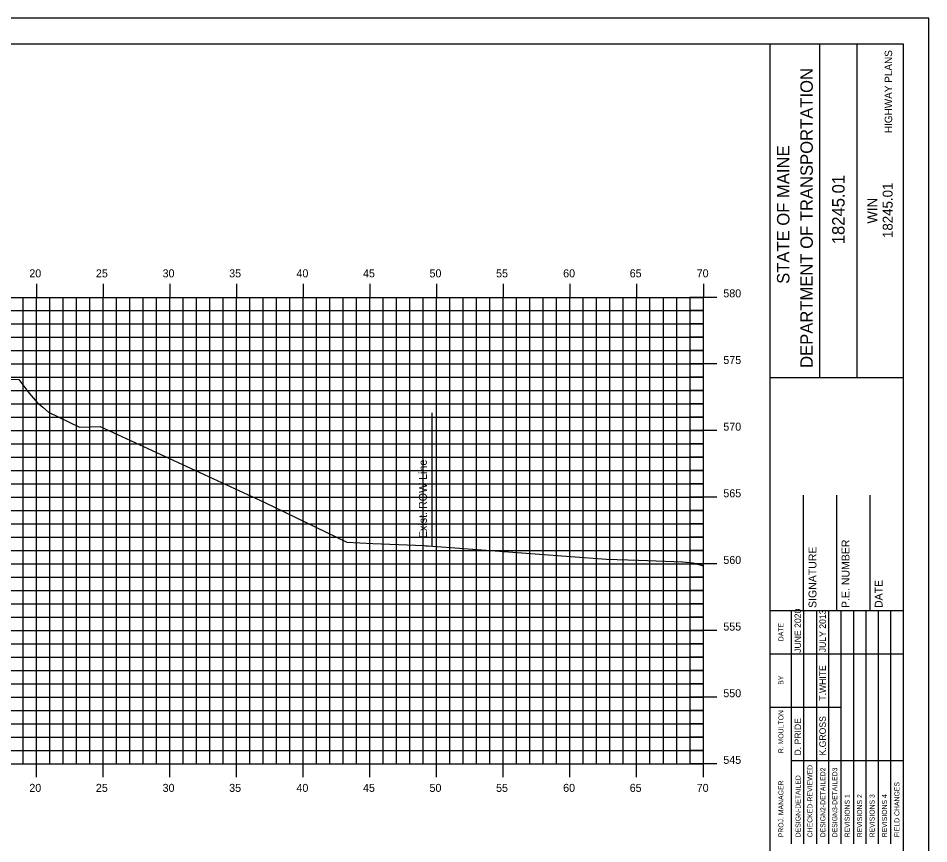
# Model space of a CAD drawing. Extents: x 1060559 to 1060729, y 779716 to 779826.
# Drawn here: x 1060660.7 to 1060729, y 779763.7 to 779825.6 of the extents above; entities that cross this region are included whole.
import ezdxf

# ---------------------------------------------------------------- set-up
doc = ezdxf.new("R2010")
doc.units = 0
for name, color, linetype in [('BORDER', 7, 'Continuous'), ('E_ROW_Line', 7, 'Continuous'), ('H_V ANNOTATION', 7, 'Continuous'), ('HIGHWAY_TITLE', 7, 'Continuous'), ('MAJOR', 7, 'Continuous'), ('MINOR', 7, 'Continuous'), ('PLOT BOUNDARY', 7, 'Continuous'), ('S_Roadway_Centerline', 7, 'Continuous'), ('S_Roadway_Edge_Pavement', 7, 'Continuous')]:
    doc.layers.add(name, color=color, linetype=linetype)

msp = doc.modelspace()

# ---------------------------------------------------------------- linework, layer by layer
at = {"layer": 'BORDER'}
for p, q in [((1060717.08, 779718.706), (1060717.08, 779823.706)), ((1060720.808, 779798.703), (1060720.808, 779823.703)), ((1060723.603, 779798.703), (1060723.603, 779823.703)), ((1060717.081, 779798.7), (1060727.08, 779798.7)), ((1060719.58, 779781.209), (1060719.58, 779789.856)), ((1060722.08, 779781.209), (1060722.08, 779789.856)), ((1060724.58, 779781.209), (1060724.58, 779789.856)), ((1060717.08, 779781.209), (1060727.08, 779781.209))]:
    msp.add_line(p, q, dxfattribs=at)
msp.add_lwpolyline([(1060567.08, 779718.706), (1060727.08, 779718.706), (1060727.08, 779823.706), (1060567.08, 779823.706)], close=True, dxfattribs=at)
for points in [[(1060718.695, 779777.959), (1060718.695, 779781.209)], [(1060719.627, 779763.712), (1060719.627, 779781.209)], [(1060720.559, 779781.209), (1060720.559, 779763.712)], [(1060721.491, 779763.712), (1060721.491, 779781.209)], [(1060722.422, 779763.712), (1060722.422, 779781.209)], [(1060723.354, 779763.712), (1060723.354, 779781.209)], [(1060724.286, 779763.712), (1060724.286, 779781.209)], [(1060725.217, 779763.712), (1060725.217, 779781.209)], [(1060726.149, 779763.712), (1060726.149, 779781.209)], [(1060718.695, 779763.712), (1060718.695, 779780.503)], [(1060717.08, 779777.959), (1060727.08, 779777.959)], [(1060717.08, 779773.959), (1060718.695, 779773.959)], [(1060718.695, 779773.959), (1060722.421, 779773.959)], [(1060718.695, 779769.959), (1060727.08, 779769.959)]]:
    msp.add_lwpolyline(points, dxfattribs=at)
at = {"layer": 'E_ROW_Line'}
msp.add_line((1060691.744, 779786.042), (1060691.744, 779796.042), dxfattribs=at)
msp.add_line((1060691.744, 779786.042), (1060691.744, 779796.042), dxfattribs=at)
at = {"layer": 'MAJOR'}
for p, q in [((1060662.079, 779805.708), (1060662.079, 779804.706)), ((1060667.079, 779805.708), (1060667.079, 779804.706)), ((1060672.079, 779805.708), (1060672.079, 779804.706)), ((1060677.079, 779805.708), (1060677.079, 779804.706)), ((1060682.079, 779805.708), (1060682.079, 779804.706)), ((1060687.079, 779805.708), (1060687.079, 779804.706)), ((1060692.079, 779805.708), (1060692.079, 779804.706)), ((1060697.079, 779805.708), (1060697.079, 779804.706)), ((1060702.079, 779805.708), (1060702.079, 779804.706)), ((1060707.079, 779805.708), (1060707.079, 779804.706)), ((1060712.079, 779805.708), (1060712.079, 779804.706)), ((1060572.079, 779804.706), (1060712.079, 779804.706)), ((1060572.079, 779804.706), (1060712.079, 779804.706)), ((1060662.079, 779769.706), (1060662.079, 779804.706)), ((1060667.079, 779769.706), (1060667.079, 779804.706)), ((1060672.079, 779769.706), (1060672.079, 779804.706)), ((1060677.079, 779769.706), (1060677.079, 779804.706)), ((1060682.079, 779769.706), (1060682.079, 779804.706)), ((1060687.079, 779769.706), (1060687.079, 779804.706)), ((1060692.079, 779769.706), (1060692.079, 779804.706)), ((1060697.079, 779769.706), (1060697.079, 779804.706)), ((1060702.079, 779769.706), (1060702.079, 779804.706)), ((1060707.079, 779769.706), (1060707.079, 779804.706)), ((1060713.081, 779804.706), (1060711.077, 779804.706)), ((1060712.079, 779769.706), (1060712.079, 779804.706)), ((1060712.079, 779769.706), (1060712.079, 779804.706)), ((1060572.079, 779799.706), (1060712.079, 779799.706)), ((1060713.081, 779799.706), (1060711.077, 779799.706)), ((1060572.079, 779794.706), (1060712.079, 779794.706)), ((1060713.081, 779794.706), (1060711.077, 779794.706)), ((1060572.079, 779789.706), (1060712.079, 779789.706)), ((1060713.081, 779789.706), (1060711.077, 779789.706)), ((1060572.079, 779784.706), (1060712.079, 779784.706)), ((1060713.081, 779784.706), (1060711.077, 779784.706)), ((1060572.079, 779779.706), (1060712.079, 779779.706)), ((1060713.081, 779779.706), (1060711.077, 779779.706)), ((1060572.079, 779774.706), (1060712.079, 779774.706)), ((1060713.081, 779774.706), (1060711.077, 779774.706)), ((1060572.079, 779769.706), (1060712.079, 779769.706)), ((1060572.079, 779769.706), (1060712.079, 779769.706)), ((1060662.079, 779768.704), (1060662.079, 779769.706)), ((1060667.079, 779768.704), (1060667.079, 779769.706)), ((1060672.079, 779768.704), (1060672.079, 779769.706)), ((1060677.079, 779768.704), (1060677.079, 779769.706)), ((1060682.079, 779768.704), (1060682.079, 779769.706)), ((1060687.079, 779768.704), (1060687.079, 779769.706)), ((1060692.079, 779768.704), (1060692.079, 779769.706)), ((1060697.079, 779768.704), (1060697.079, 779769.706)), ((1060702.079, 779768.704), (1060702.079, 779769.706)), ((1060707.079, 779768.704), (1060707.079, 779769.706)), ((1060713.081, 779769.706), (1060711.077, 779769.706)), ((1060712.079, 779768.704), (1060712.079, 779769.706))]:
    msp.add_line(p, q, dxfattribs=at)
at = {"layer": 'MINOR'}
for p, q in [((1060661.079, 779769.706), (1060661.079, 779804.706)), ((1060663.079, 779769.706), (1060663.079, 779804.706)), ((1060664.079, 779769.706), (1060664.079, 779804.706)), ((1060665.079, 779769.706), (1060665.079, 779804.706)), ((1060666.079, 779769.706), (1060666.079, 779804.706)), ((1060668.079, 779769.706), (1060668.079, 779804.706)), ((1060669.079, 779769.706), (1060669.079, 779804.706)), ((1060670.079, 779769.706), (1060670.079, 779804.706)), ((1060671.079, 779769.706), (1060671.079, 779804.706)), ((1060673.079, 779769.706), (1060673.079, 779804.706)), ((1060674.079, 779769.706), (1060674.079, 779804.706)), ((1060675.079, 779769.706), (1060675.079, 779804.706)), ((1060676.079, 779769.706), (1060676.079, 779804.706)), ((1060678.079, 779769.706), (1060678.079, 779804.706)), ((1060679.079, 779769.706), (1060679.079, 779804.706)), ((1060680.079, 779769.706), (1060680.079, 779804.706)), ((1060681.079, 779769.706), (1060681.079, 779804.706)), ((1060683.079, 779769.706), (1060683.079, 779804.706)), ((1060684.079, 779769.706), (1060684.079, 779804.706)), ((1060685.079, 779769.706), (1060685.079, 779804.706)), ((1060686.079, 779769.706), (1060686.079, 779804.706)), ((1060688.079, 779769.706), (1060688.079, 779804.706)), ((1060689.079, 779769.706), (1060689.079, 779804.706)), ((1060690.079, 779769.706), (1060690.079, 779804.706)), ((1060691.079, 779769.706), (1060691.079, 779804.706)), ((1060693.079, 779769.706), (1060693.079, 779804.706)), ((1060694.079, 779769.706), (1060694.079, 779804.706)), ((1060695.079, 779769.706), (1060695.079, 779804.706)), ((1060696.079, 779769.706), (1060696.079, 779804.706)), ((1060698.079, 779769.706), (1060698.079, 779804.706)), ((1060699.079, 779769.706), (1060699.079, 779804.706)), ((1060700.079, 779769.706), (1060700.079, 779804.706)), ((1060701.079, 779769.706), (1060701.079, 779804.706)), ((1060703.079, 779769.706), (1060703.079, 779804.706)), ((1060704.079, 779769.706), (1060704.079, 779804.706)), ((1060705.079, 779769.706), (1060705.079, 779804.706)), ((1060706.079, 779769.706), (1060706.079, 779804.706)), ((1060708.079, 779769.706), (1060708.079, 779804.706)), ((1060709.079, 779769.706), (1060709.079, 779804.706)), ((1060710.079, 779769.706), (1060710.079, 779804.706)), ((1060711.079, 779769.706), (1060711.079, 779804.706)), ((1060572.079, 779803.706), (1060712.079, 779803.706)), ((1060712.079, 779803.706), (1060711.077, 779803.706)), ((1060572.079, 779802.706), (1060712.079, 779802.706)), ((1060712.079, 779802.706), (1060711.077, 779802.706)), ((1060572.079, 779801.706), (1060712.079, 779801.706)), ((1060712.079, 779801.706), (1060711.077, 779801.706)), ((1060572.079, 779800.706), (1060712.079, 779800.706)), ((1060712.079, 779800.706), (1060711.077, 779800.706)), ((1060572.079, 779798.706), (1060712.079, 779798.706)), ((1060712.079, 779798.706), (1060711.077, 779798.706)), ((1060572.079, 779797.706), (1060712.079, 779797.706)), ((1060712.079, 779797.706), (1060711.077, 779797.706)), ((1060572.079, 779796.706), (1060712.079, 779796.706)), ((1060712.079, 779796.706), (1060711.077, 779796.706)), ((1060572.079, 779795.706), (1060712.079, 779795.706)), ((1060712.079, 779795.706), (1060711.077, 779795.706)), ((1060572.079, 779793.706), (1060712.079, 779793.706)), ((1060712.079, 779793.706), (1060711.077, 779793.706)), ((1060572.079, 779792.706), (1060712.079, 779792.706)), ((1060712.079, 779792.706), (1060711.077, 779792.706)), ((1060572.079, 779791.706), (1060712.079, 779791.706)), ((1060712.079, 779791.706), (1060711.077, 779791.706)), ((1060572.079, 779790.706), (1060712.079, 779790.706)), ((1060712.079, 779790.706), (1060711.077, 779790.706)), ((1060572.079, 779788.706), (1060712.079, 779788.706)), ((1060712.079, 779788.706), (1060711.077, 779788.706)), ((1060572.079, 779787.706), (1060712.079, 779787.706)), ((1060712.079, 779787.706), (1060711.077, 779787.706)), ((1060572.079, 779786.706), (1060712.079, 779786.706)), ((1060712.079, 779786.706), (1060711.077, 779786.706)), ((1060572.079, 779785.706), (1060712.079, 779785.706)), ((1060712.079, 779785.706), (1060711.077, 779785.706)), ((1060572.079, 779783.706), (1060712.079, 779783.706)), ((1060712.079, 779783.706), (1060711.077, 779783.706)), ((1060572.079, 779782.706), (1060712.079, 779782.706)), ((1060712.079, 779782.706), (1060711.077, 779782.706)), ((1060572.079, 779781.706), (1060712.079, 779781.706)), ((1060712.079, 779781.706), (1060711.077, 779781.706)), ((1060572.079, 779780.706), (1060712.079, 779780.706)), ((1060712.079, 779780.706), (1060711.077, 779780.706)), ((1060572.079, 779778.706), (1060712.079, 779778.706)), ((1060712.079, 779778.706), (1060711.077, 779778.706)), ((1060572.079, 779777.706), (1060712.079, 779777.706)), ((1060712.079, 779777.706), (1060711.077, 779777.706)), ((1060572.079, 779776.706), (1060712.079, 779776.706)), ((1060712.079, 779776.706), (1060711.077, 779776.706)), ((1060572.079, 779775.706), (1060712.079, 779775.706)), ((1060712.079, 779775.706), (1060711.077, 779775.706)), ((1060572.079, 779773.706), (1060712.079, 779773.706)), ((1060712.079, 779773.706), (1060711.077, 779773.706)), ((1060572.079, 779772.706), (1060712.079, 779772.706)), ((1060712.079, 779772.706), (1060711.077, 779772.706)), ((1060572.079, 779771.706), (1060712.079, 779771.706)), ((1060712.079, 779771.706), (1060711.077, 779771.706)), ((1060572.079, 779770.706), (1060712.079, 779770.706)), ((1060712.079, 779770.706), (1060711.077, 779770.706))]:
    msp.add_line(p, q, dxfattribs=at)
at = {"layer": 'PLOT BOUNDARY'}
msp.add_lwpolyline([(1060558.986, 779715.646), (1060728.986, 779715.646), (1060728.986, 779825.646), (1060558.986, 779825.646)], close=True, dxfattribs=at)
at = {"layer": 'S_Roadway_Centerline'}
msp.add_lwpolyline([(1060659.696, 779798.557), (1060660.735, 779798.532), (1060661.355, 779797.754), (1060661.51, 779797.525), (1060662.125, 779796.817), (1060662.535, 779796.463), (1060662.979, 779796.086), (1060665.304, 779794.962), (1060666.847, 779795.02), (1060679.203, 779789.313), (1060685.337, 779786.341), (1060687.301, 779786.237), (1060691.149, 779786.077), (1060691.257, 779786.07), (1060691.45, 779786.063), (1060704.809, 779785.066), (1060707.21, 779784.98), (1060710.541, 779784.851), (1060711.284, 779784.783), (1060712.079, 779784.566)], dxfattribs=at)
at = {"layer": 'S_Roadway_Edge_Pavement'}
msp.add_lwpolyline([(1060660.735, 779798.532), (1060660.735, 779798.532)], dxfattribs=at)

# ---------------------------------------------------------------- texts
at = {"layer": 'BORDER'}
for s, height, p in [('DEPARTMENT OF TRANSPORTATION', 0.93176, (1060720.287, 779799.412)), ('STATE OF MAINE', 0.93176, (1060718.535, 779805.718)), ('18245.01', 0.9318, (1060722.672, 779808.691)), ('18245.01', 0.7453, (1060726.275, 779809.156)), ('WIN', 0.7453, (1060725.116, 779810.236)), ('P.E. NUMBER', 0.59055, (1060723.04, 779781.401)), ('SIGNATURE', 0.5906, (1060720.56, 779781.401)), ('DATE', 0.5906, (1060725.521, 779781.401)), ('JUNE 2020', 0.4845, (1060719.403, 779778.034)), ('JULY 2013', 0.4845, (1060721.266, 779778.08)), ('DATE', 0.3714, (1060718.084, 779778.914)), ('T.WHITE', 0.4845, (1060721.266, 779774.444)), ('BY', 0.3714, (1060718.084, 779775.644)), ('R. MOULTON', 0.3727, (1060718.084, 779770.511)), ('D. PRIDE', 0.4845, (1060719.403, 779770.332)), ('K.GROSS', 0.4845, (1060721.266, 779770.332)), ('CHECKED-REVIEWED', 0.37275, (1060720.261, 779764.197)), ('DESIGN-DETAILED', 0.37275, (1060719.366, 779764.197)), ('DESIGN2-DETAILED2', 0.37275, (1060721.23, 779764.197)), ('DESIGN3-DETAILED3', 0.37275, (1060722.124, 779764.197)), ('PROJ. MANAGER', 0.37275, (1060718.084, 779764.197)), ('FIELD CHANGES', 0.37275, (1060726.782, 779764.197)), ('REVISIONS 3', 0.37275, (1060724.919, 779764.197)), ('REVISIONS 4', 0.37275, (1060725.851, 779764.197)), ('REVISIONS 1', 0.37275, (1060723.056, 779764.197)), ('REVISIONS 2', 0.37275, (1060723.987, 779764.197))]:
    msp.add_text(s, height=height, rotation=90, dxfattribs=at).set_placement(p)
at = {"layer": 'E_ROW_Line'}
msp.add_text('Exist. ROW Line', height=0.6, rotation=90, dxfattribs=at).set_placement((1060691.344, 779786.642))
at = {"layer": 'H_V ANNOTATION'}
for s, p in [('20', (1060661.533, 779806.206)), ('25', (1060666.525, 779806.206)), ('30', (1060671.528, 779806.206)), ('35', (1060676.52, 779806.206)), ('40', (1060681.566, 779806.206)), ('45', (1060686.558, 779806.206)), ('50', (1060691.544, 779806.206)), ('55', (1060696.536, 779806.206)), ('60', (1060701.566, 779806.206)), ('65', (1060706.558, 779806.206)), ('70', (1060711.582, 779806.206)), ('580', (1060713.579, 779804.706)), ('575', (1060713.579, 779799.706)), ('570', (1060713.579, 779794.706)), ('565', (1060713.579, 779789.706)), ('560', (1060713.579, 779784.706)), ('555', (1060713.579, 779779.706)), ('550', (1060713.579, 779774.706)), ('545', (1060713.579, 779769.706)), ('20', (1060661.533, 779767.606)), ('25', (1060666.525, 779767.606)), ('30', (1060671.528, 779767.606)), ('35', (1060676.52, 779767.606)), ('40', (1060681.566, 779767.606)), ('45', (1060686.558, 779767.606)), ('50', (1060691.544, 779767.606)), ('55', (1060696.536, 779767.606)), ('60', (1060701.566, 779767.606)), ('65', (1060706.558, 779767.606)), ('70', (1060711.582, 779767.606))]:
    msp.add_text(s, height=0.6, dxfattribs=at).set_placement(p)
at = {"layer": 'HIGHWAY_TITLE'}
msp.add_text('HIGHWAY PLANS', height=0.55901, rotation=90, dxfattribs=at).set_placement((1060726.238, 779817.021))

doc.saveas('drawing.dxf')
